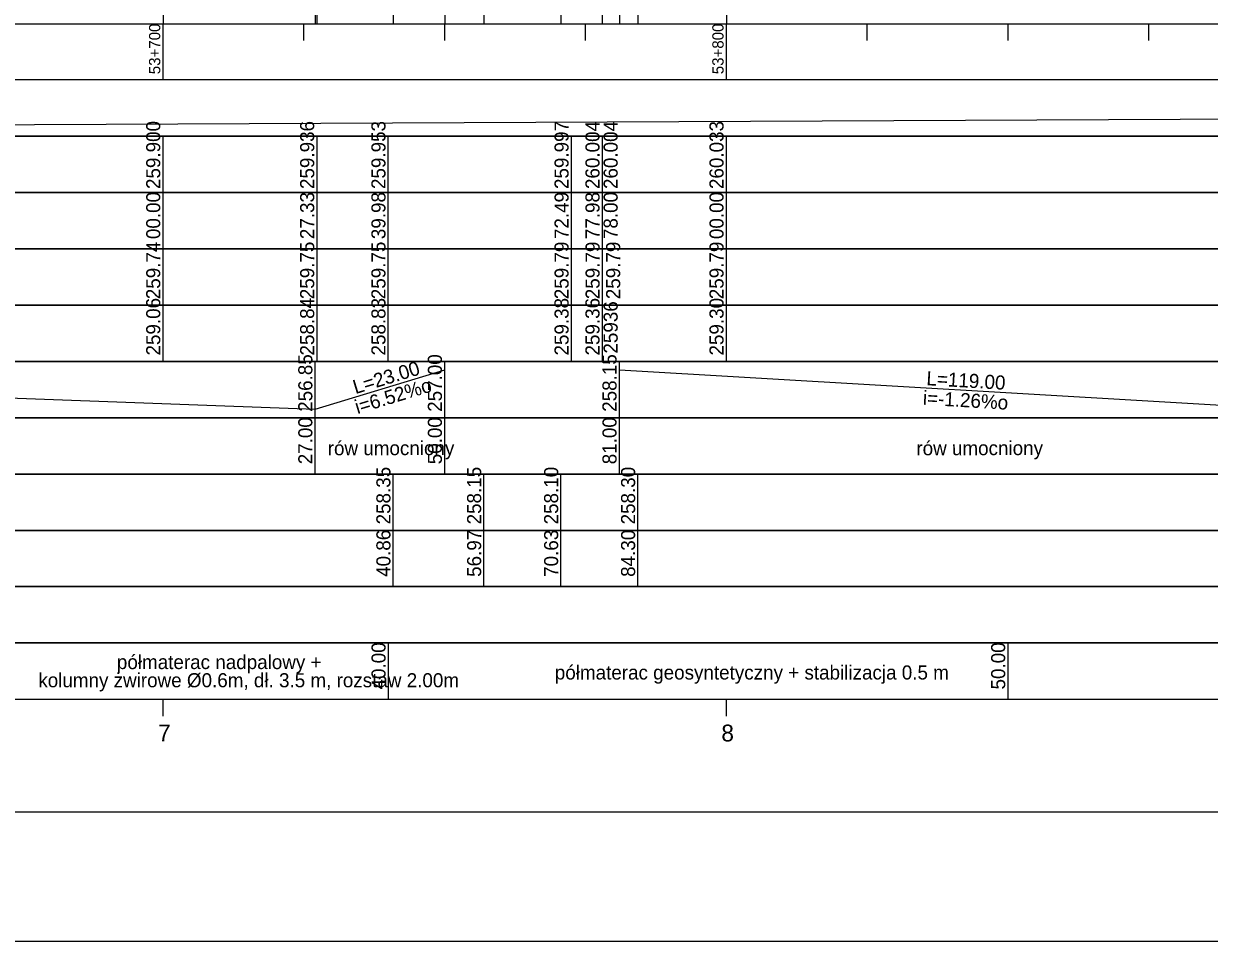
# Model space of a CAD drawing. Extents: x 6445630 to 6518227, y 5499240 to 5511716.
# Drawn here: x 6452906.5 to 6453116.9, y 5508966.7 to 5509129.7 of the extents above; entities that cross this region are included whole.
import ezdxf

# ---------------------------------------------------------------- set-up
doc = ezdxf.new("R2010")
doc.units = 0
for name, color, linetype in [('TOR_PROF-drenokolektory', 7, 'Continuous'), ('TOR_PROF-obiekty+opisy', 7, 'Continuous'), ('TOR_PROF-opisy pomocnicze', 7, 'Continuous'), ('TOR_PROF-rowy otwarte', 7, 'Continuous'), ('TOR_PROF-tabelka-geometria T1', 7, 'Continuous'), ('TOR_PROF-tabelka-kilometracja', 7, 'Continuous'), ('TOR_PROF-tabelka-odleglosci T1', 7, 'Continuous'), ('TOR_PROF-tabelka-pochylenia proj T1', 7, 'Continuous'), ('TOR_PROF-tabelka-rodzaj rowu T1', 7, 'Continuous'), ('TOR_PROF-tabelka-rodzaj rurociagow T1', 7, 'Continuous'), ('TOR_PROF-tabelka-rowyT1', 7, 'Continuous'), ('TOR_PROF-tabelka-rurociagi T1', 7, 'Continuous'), ('TOR_PROF-tabelka-rzedne istn T1', 7, 'Continuous'), ('TOR_PROF-tabelka-rzedne proj T1', 7, 'Continuous'), ('TOR_PROF-tabelka-teren istniejacy T1', 7, 'Continuous'), ('TOR_PROF-tabelka-warstwa ochronna T1', 7, 'Continuous'), ('TOR_PROF-tor projektowany', 7, 'Continuous'), ('TOR_PROF-uklad odniesienia', 7, 'Continuous'), ('TOR_PROF-warstwa ochronna', 7, 'Continuous'), ('TOR_RAMKI-MASKA WYCIECIA', 7, 'Continuous')]:
    doc.layers.add(name, color=color, linetype=linetype)

msp = doc.modelspace()

# ---------------------------------------------------------------- linework, layer by layer
at = {"layer": 'TOR_PROF-drenokolektory'}
for points in [[(6452972.07, 5509156.49), (6452972.07, 5509134.74), (6452972.07, 5509129.74), (6452972.07, 5509129.74)], [(6452972.07, 5509156.49), (6452972.07, 5509134.74), (6452972.07, 5509129.74), (6452972.07, 5509129.74)], [(6453015.51, 5509156.24), (6453015.51, 5509134.74), (6453015.51, 5509129.74), (6453015.51, 5509129.74)], [(6453015.51, 5509156.24), (6453015.51, 5509134.74), (6453015.51, 5509129.74), (6453015.51, 5509129.74)], [(6452988.18, 5509155.49), (6452988.18, 5509134.74), (6452988.18, 5509129.74), (6452988.18, 5509129.74)], [(6452988.18, 5509155.49), (6452988.18, 5509134.74), (6452988.18, 5509129.74), (6452988.18, 5509129.74)], [(6452988.18, 5509155.49), (6452988.18, 5509134.74), (6452988.18, 5509129.74), (6452988.18, 5509129.74)], [(6453001.85, 5509155.24), (6453001.85, 5509134.74), (6453001.85, 5509129.74), (6453001.85, 5509129.74)], [(6453001.85, 5509155.24), (6453001.85, 5509134.74), (6453001.85, 5509129.74), (6453001.85, 5509129.74)], [(6453001.85, 5509155.24), (6453001.85, 5509134.74), (6453001.85, 5509129.74), (6453001.85, 5509129.74)]]:
    msp.add_lwpolyline(points, dxfattribs=at)
at = {"layer": 'TOR_PROF-obiekty+opisy'}
for p, q in [((6452958.54, 5509129.74), (6452958.54, 5509194.42)), ((6453009.19, 5509129.74), (6453009.19, 5509194.76))]:
    msp.add_line(p, q, dxfattribs=at)
at = {"layer": 'TOR_PROF-opisy pomocnicze'}
for p, q in [((6453012.21, 5509155.49), (6453012.21, 5509129.74)), ((6452981.21, 5509149.74), (6452981.21, 5509129.74)), ((6452958.21, 5509148.99), (6452958.21, 5509129.74))]:
    msp.add_line(p, q, dxfattribs=at)
at = {"layer": 'TOR_PROF-rowy otwarte'}
for points in [[(6453012.21, 5509155.49), (6453012.21, 5509134.74), (6453012.21, 5509129.74), (6453012.21, 5509129.74)], [(6452981.21, 5509149.74), (6452981.21, 5509134.74), (6452981.21, 5509129.74), (6452981.21, 5509129.74)], [(6452958.21, 5509148.99), (6452958.21, 5509134.74), (6452958.21, 5509129.74), (6452958.21, 5509129.74)]]:
    msp.add_lwpolyline(points, dxfattribs=at)
at = {"layer": 'TOR_PROF-tabelka-geometria T1'}
for points in [[(6452331.21, 5508989.74), (6462728.4, 5508989.74)], [(6452331.21, 5508989.74), (6462731.21, 5508989.74)]]:
    msp.add_lwpolyline(points, dxfattribs=at)
at = {"layer": 'TOR_PROF-tabelka-kilometracja'}
for points in [[(6452931.21, 5509006.74), (6452931.21, 5509009.74)], [(6453031.21, 5509006.74), (6453031.21, 5509009.74)]]:
    msp.add_lwpolyline(points, dxfattribs=at)
at = {"layer": 'TOR_PROF-tabelka-odleglosci T1'}
msp.add_lwpolyline([(6452331.21, 5509089.74), (6462731.21, 5509089.74), (6462731.21, 5509099.74), (6452331.21, 5509099.74)], close=True, dxfattribs=at)
for points in [[(6452931.21, 5509089.74), (6452931.21, 5509099.74)], [(6452958.54, 5509089.74), (6452958.54, 5509099.74)], [(6452971.19, 5509089.74), (6452971.19, 5509099.74)], [(6453003.7, 5509089.74), (6453003.7, 5509099.74)], [(6453009.19, 5509089.74), (6453009.19, 5509099.74)], [(6453009.21, 5509089.74), (6453009.21, 5509099.74)], [(6453031.21, 5509089.74), (6453031.21, 5509099.74)]]:
    msp.add_lwpolyline(points, dxfattribs=at)
at = {"layer": 'TOR_PROF-tabelka-pochylenia proj T1'}
msp.add_lwpolyline([(6452331.21, 5509109.74), (6462731.21, 5509109.74), (6462731.21, 5509119.74), (6452331.21, 5509119.74)], close=True, dxfattribs=at)
msp.add_lwpolyline([(6452781.21, 5509111.24), (6454281.21, 5509118.24)], dxfattribs=at)
at = {"layer": 'TOR_PROF-tabelka-rodzaj rowu T1'}
for points in [[(6452331.21, 5509049.74), (6462731.21, 5509049.74), (6462731.21, 5509059.74), (6452331.21, 5509059.74)], [(6452331.21, 5509029.74), (6462731.21, 5509029.74), (6462731.21, 5509039.74), (6452331.21, 5509039.74)]]:
    msp.add_lwpolyline(points, close=True, dxfattribs=at)
for points in [[(6452958.21, 5509049.74), (6452958.21, 5509059.74)], [(6452981.21, 5509049.74), (6452981.21, 5509059.74)], [(6453012.21, 5509049.74), (6453012.21, 5509059.74)], [(6452972.07, 5509029.74), (6452972.07, 5509039.74)], [(6452988.18, 5509029.74), (6452988.18, 5509039.74)], [(6453001.85, 5509029.74), (6453001.85, 5509039.74)], [(6453015.51, 5509029.74), (6453015.51, 5509039.74)]]:
    msp.add_lwpolyline(points, dxfattribs=at)
at = {"layer": 'TOR_PROF-tabelka-rowyT1'}
msp.add_lwpolyline([(6452331.21, 5509059.74), (6462731.21, 5509059.74), (6462731.21, 5509069.74), (6452331.21, 5509069.74)], close=True, dxfattribs=at)
for points in [[(6452958.21, 5509059.74), (6452958.21, 5509069.74)], [(6452981.21, 5509059.74), (6452981.21, 5509069.74)], [(6453012.21, 5509059.74), (6453012.21, 5509069.74)], [(6452769.21, 5509068.24), (6452958.21, 5509061.24)], [(6452958.21, 5509061.24), (6452981.21, 5509068.24)], [(6453012.21, 5509068.24), (6453131.21, 5509061.24)]]:
    msp.add_lwpolyline(points, dxfattribs=at)
at = {"layer": 'TOR_PROF-tabelka-rurociagi T1'}
msp.add_lwpolyline([(6452331.21, 5509039.74), (6462731.21, 5509039.74), (6462731.21, 5509049.74), (6452331.21, 5509049.74)], close=True, dxfattribs=at)
for points in [[(6452972.07, 5509039.74), (6452972.07, 5509049.74)], [(6452988.18, 5509039.74), (6452988.18, 5509049.74)], [(6453001.85, 5509039.74), (6453001.85, 5509049.74)], [(6453015.51, 5509039.74), (6453015.51, 5509049.74)]]:
    msp.add_lwpolyline(points, dxfattribs=at)
at = {"layer": 'TOR_PROF-tabelka-rzedne istn T1'}
msp.add_lwpolyline([(6452331.21, 5509079.74), (6462731.21, 5509079.74), (6462731.21, 5509089.74), (6452331.21, 5509089.74)], close=True, dxfattribs=at)
for points in [[(6452931.21, 5509079.74), (6452931.21, 5509089.74)], [(6452958.54, 5509079.74), (6452958.54, 5509089.74)], [(6452971.19, 5509079.74), (6452971.19, 5509089.74)], [(6453003.7, 5509079.74), (6453003.7, 5509089.74)], [(6453009.19, 5509079.74), (6453009.19, 5509089.74)], [(6453031.21, 5509079.74), (6453031.21, 5509089.74)], [(6452931.21, 5509069.74), (6452931.21, 5509079.74)], [(6452931.21, 5509069.74), (6452931.21, 5509079.74)], [(6452931.21, 5509069.74), (6452931.21, 5509079.74)], [(6452931.21, 5509069.74), (6452931.21, 5509079.74)], [(6452931.21, 5509069.74), (6452931.21, 5509079.74)], [(6452958.54, 5509069.74), (6452958.54, 5509079.74)], [(6452971.19, 5509069.74), (6452971.19, 5509079.74)], [(6453003.7, 5509069.74), (6453003.7, 5509079.74)], [(6453009.19, 5509069.74), (6453009.19, 5509079.74)], [(6453031.21, 5509069.74), (6453031.21, 5509079.74)], [(6453031.21, 5509069.74), (6453031.21, 5509079.74)], [(6453031.21, 5509069.74), (6453031.21, 5509079.74)], [(6453031.21, 5509069.74), (6453031.21, 5509079.74)], [(6453031.21, 5509069.74), (6453031.21, 5509079.74)]]:
    msp.add_lwpolyline(points, dxfattribs=at)
at = {"layer": 'TOR_PROF-tabelka-rzedne proj T1'}
msp.add_lwpolyline([(6452331.21, 5509099.74), (6462731.21, 5509099.74), (6462731.21, 5509109.74), (6452331.21, 5509109.74)], close=True, dxfattribs=at)
for points in [[(6452931.21, 5509099.74), (6452931.21, 5509109.74)], [(6452958.54, 5509099.74), (6452958.54, 5509109.74)], [(6452971.19, 5509099.74), (6452971.19, 5509109.74)], [(6453003.7, 5509099.74), (6453003.7, 5509109.74)], [(6453009.19, 5509099.74), (6453009.19, 5509109.74)], [(6453009.21, 5509099.74), (6453009.21, 5509109.74)], [(6453031.21, 5509099.74), (6453031.21, 5509109.74)]]:
    msp.add_lwpolyline(points, dxfattribs=at)
at = {"layer": 'TOR_PROF-tabelka-teren istniejacy T1'}
msp.add_lwpolyline([(6452331.21, 5509069.74), (6462731.21, 5509069.74), (6462731.21, 5509079.74), (6452331.21, 5509079.74)], close=True, dxfattribs=at)
msp.add_lwpolyline([(6452331.21, 5509069.74), (6462731.21, 5509069.74), (6462731.21, 5509079.74), (6452331.21, 5509079.74)], close=True, dxfattribs=at)
msp.add_lwpolyline([(6452331.21, 5509069.74), (6462731.21, 5509069.74), (6462731.21, 5509079.74), (6452331.21, 5509079.74)], close=True, dxfattribs=at)
msp.add_lwpolyline([(6452331.21, 5509069.74), (6462731.21, 5509069.74), (6462731.21, 5509079.74), (6452331.21, 5509079.74)], close=True, dxfattribs=at)
msp.add_lwpolyline([(6452331.21, 5509069.74), (6462731.21, 5509069.74), (6462731.21, 5509079.74), (6452331.21, 5509079.74)], close=True, dxfattribs=at)
at = {"layer": 'TOR_PROF-tabelka-warstwa ochronna T1'}
msp.add_lwpolyline([(6452331.21, 5509019.74), (6462731.21, 5509019.74), (6462731.21, 5509029.74), (6452331.21, 5509029.74)], close=True, dxfattribs=at)
at = {"layer": 'TOR_PROF-tor projektowany'}
for points in [[(6452931.21, 5509164.24), (6452931.21, 5509134.74), (6452931.21, 5509129.74), (6452931.21, 5509129.74)], [(6452931.21, 5509164.24), (6452931.21, 5509134.74), (6452931.21, 5509129.74), (6452931.21, 5509129.74)], [(6453031.21, 5509164.9), (6453031.21, 5509134.74), (6453031.21, 5509129.74), (6453031.21, 5509129.74)], [(6453031.21, 5509164.9), (6453031.21, 5509134.74), (6453031.21, 5509129.74), (6453031.21, 5509129.74)]]:
    msp.add_lwpolyline(points, dxfattribs=at)
at = {"layer": 'TOR_PROF-uklad odniesienia'}
for p, q in [((6452331.21, 5509129.74), (6462731.21, 5509129.74)), ((6452931.21, 5509119.74), (6452931.21, 5509129.74)), ((6452956.21, 5509126.74), (6452956.21, 5509129.74)), ((6452981.21, 5509126.74), (6452981.21, 5509129.74)), ((6453006.21, 5509126.74), (6453006.21, 5509129.74)), ((6453031.21, 5509119.74), (6453031.21, 5509129.74)), ((6453056.21, 5509126.74), (6453056.21, 5509129.74)), ((6453081.21, 5509126.74), (6453081.21, 5509129.74)), ((6453106.21, 5509126.74), (6453106.21, 5509129.74))]:
    msp.add_line(p, q, dxfattribs=at)
at = {"layer": 'TOR_PROF-warstwa ochronna'}
msp.add_lwpolyline([(6452331.21, 5509009.74), (6462731.21, 5509009.74), (6462731.21, 5509019.74), (6452331.21, 5509019.74)], close=True, dxfattribs=at)
for points in [[(6452971.21, 5509009.74), (6452971.21, 5509019.74)], [(6453081.21, 5509009.74), (6453081.21, 5509019.74)]]:
    msp.add_lwpolyline(points, dxfattribs=at)
at = {"layer": 'TOR_RAMKI-MASKA WYCIECIA'}
msp.add_lwpolyline([(6452263.34, 5508966.75), (6454333.34, 5508966.75), (6454333.34, 5509253.75), (6452263.34, 5509253.75)], close=True, dxfattribs=at)

# ---------------------------------------------------------------- texts
at = {"layer": 'TOR_PROF-tabelka-kilometracja'}
for s, p in [('7', (6452930.32, 5509002.24)), ('8', (6453030.32, 5509002.24))]:
    msp.add_text(s, height=3, dxfattribs=at).set_placement(p)
at = {"layer": 'TOR_PROF-tabelka-odleglosci T1'}
for s, p in [('00.00', (6452930.71, 5509091.48)), ('27.33', (6452958.04, 5509091.47)), ('39.98', (6452970.69, 5509091.47)), ('72.49', (6453003.2, 5509091.48)), ('77.98', (6453008.69, 5509091.47)), ('78.00', (6453011.91, 5509091.48)), ('00.00', (6453030.71, 5509091.48))]:
    msp.add_text(s, height=2.5, rotation=90, dxfattribs=at).set_placement(p)
at = {"layer": 'TOR_PROF-tabelka-rodzaj rowu T1'}
for s, p in [('27.00', (6452957.71, 5509051.48)), ('50.00', (6452980.71, 5509051.48)), ('81.00', (6453011.71, 5509051.48))]:
    msp.add_text(s, height=2.5, rotation=90, dxfattribs=at).set_placement(p)
at = {"layer": 'TOR_PROF-tabelka-rodzaj rurociagow T1'}
for s, p in [('40.86', (6452971.57, 5509031.48)), ('56.97', (6452987.68, 5509031.48)), ('70.63', (6453001.35, 5509031.48)), ('84.30', (6453015.01, 5509031.48))]:
    msp.add_text(s, height=2.5, rotation=90, dxfattribs=at).set_placement(p)
at = {"layer": 'TOR_PROF-tabelka-rowyT1'}
for s, rotation, p in [('256.85', 90, (6452957.71, 5509060.8)), ('L=23.00', 16.9275, (6452965.36, 5509063.93)), ('257.00', 90, (6452980.71, 5509060.8)), ('258.15', 90, (6453011.71, 5509060.8)), ('L=119.00', 356.6335, (6453066.67, 5509065.53)), ('i=6.52%o', 16.9275, (6452965.71, 5509060.38)), ('i=-1.26%o', 356.6335, (6453066.04, 5509062.06)), ('rów umocniony', 0.087, (6452960.44, 5509053.08)), ('rów umocniony', 0.087, (6453064.94, 5509053.08))]:
    msp.add_text(s, height=2.5, rotation=rotation, dxfattribs=at).set_placement(p)
at = {"layer": 'TOR_PROF-tabelka-rurociagi T1'}
for s, p in [('258.35', (6452971.57, 5509040.8)), ('258.15', (6452987.68, 5509040.8)), ('258.10', (6453001.35, 5509040.8)), ('258.30', (6453015.01, 5509040.8))]:
    msp.add_text(s, height=2.5, rotation=90, dxfattribs=at).set_placement(p)
at = {"layer": 'TOR_PROF-tabelka-rzedne istn T1'}
for s, p in [('259.74', (6452930.71, 5509080.8)), ('259.75', (6452958.04, 5509080.8)), ('259.75', (6452970.69, 5509080.8)), ('259.79', (6453003.2, 5509080.8)), ('259.79', (6453008.71, 5509080.8)), ('259.79', (6453012.36, 5509080.8)), ('259.79', (6453030.71, 5509080.8)), ('259.06', (6452930.71, 5509070.8)), ('258.84', (6452958.04, 5509070.8)), ('258.83', (6452970.69, 5509070.8)), ('259.38', (6453003.2, 5509070.8)), ('259.36', (6453008.69, 5509070.8)), ('25936', (6453011.91, 5509071.14)), ('259.30', (6453030.71, 5509070.8))]:
    msp.add_text(s, height=2.5, rotation=90, dxfattribs=at).set_placement(p)
at = {"layer": 'TOR_PROF-tabelka-rzedne proj T1'}
for s, p in [('259.900', (6452930.71, 5509100.37)), ('259.936', (6452958.04, 5509100.37)), ('259.953', (6452970.69, 5509100.37)), ('259.997', (6453003.2, 5509100.37)), ('260.004', (6453008.69, 5509100.37)), ('260.004', (6453011.91, 5509100.37)), ('260.033', (6453030.71, 5509100.37))]:
    msp.add_text(s, height=2.5, rotation=90, dxfattribs=at).set_placement(p)
at = {"layer": 'TOR_PROF-uklad odniesienia'}
for s, p in [('53+700', (6452930.71, 5509120.76)), ('53+800', (6453030.71, 5509120.76))]:
    msp.add_text(s, height=2, rotation=90, dxfattribs=at).set_placement(p)
at = {"layer": 'TOR_PROF-warstwa ochronna'}
for s, p in [('40.00', (6452970.71, 5509011.48)), ('50.00', (6453080.71, 5509011.48))]:
    msp.add_text(s, height=2.5, rotation=90, dxfattribs=at).set_placement(p)
for s, p in [('półmaterac nadpalowy +', (6452923.01, 5509015.1)), ('półmaterac geosyntetyczny + stabilizacja 0.5 m', (6453000.75, 5509013.25)), ('kolumny żwirowe Ø0.6m, dł. 3.5 m, rozstaw 2.00m', (6452909.06, 5509011.87))]:
    msp.add_text(s, height=2.5, dxfattribs=at).set_placement(p)

doc.saveas('drawing.dxf')
